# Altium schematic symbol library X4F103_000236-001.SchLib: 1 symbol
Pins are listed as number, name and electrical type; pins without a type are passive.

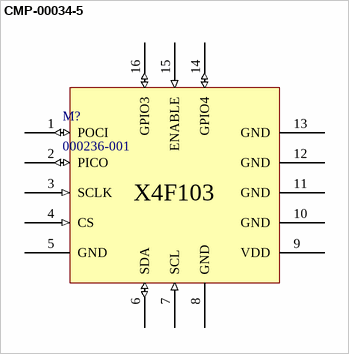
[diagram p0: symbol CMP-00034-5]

## CMP-00034-5
designator M?, comment 000236-001
Novelda X4F103; Manufacturer: Novelda AS
footprint X4F103 (X4F103 Footprint)
pins: 1 POCI (io), 2 PICO (io), 3 SCLK (in), 4 CS (in), 5 GND (power), 6 SDA (io), 7 SCL (in), 8 GND (power), 9 VDD (power), 10 GND (power), 11 GND (power), 12 GND (power), 13 GND (power), 14 GPIO4 (io), 15 ENABLE (in), 16 GPIO3 (io)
